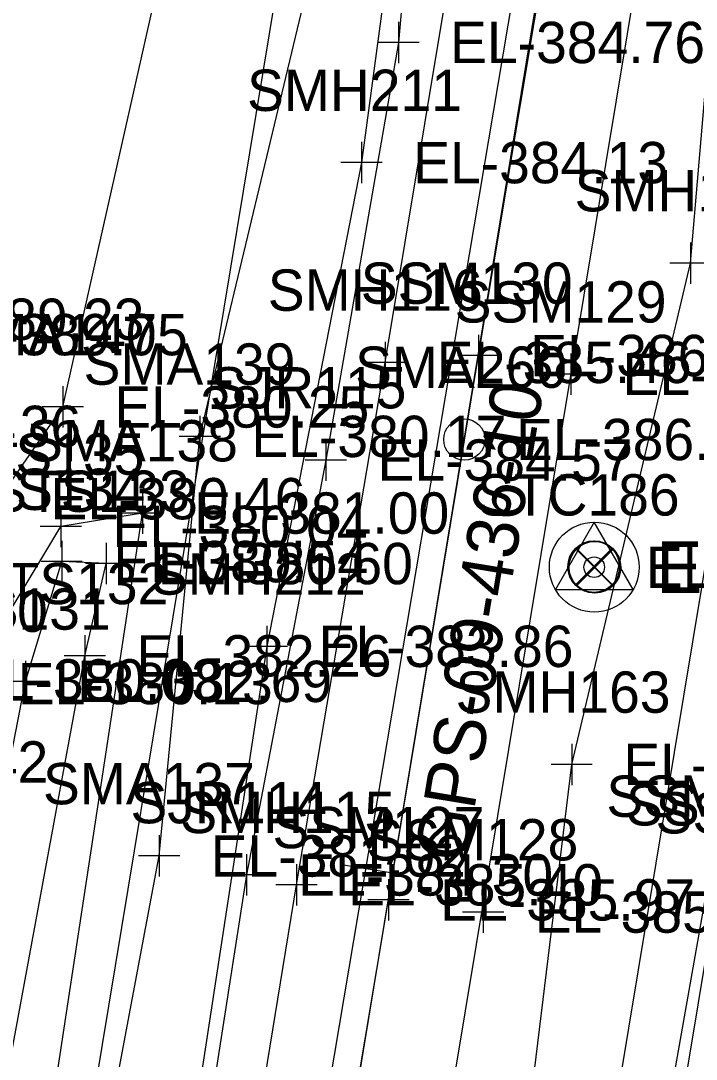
# Model space of a CAD drawing. Extents: x 1189978 to 1314812, y 571533 to 629339.
# Drawn here: x 1217500.6 to 1217566, y 621413.5 to 621514.1 of the extents above; entities that cross this region are included whole.
import ezdxf

# ---------------------------------------------------------------- set-up
doc = ezdxf.new("R2010")
doc.units = 0
for name, color, linetype in [('SURVEY - CENTERLINE - Preliminary', 7, 'Continuous'), ('SURVEY - CENTERLINE - Preliminary Text', 7, 'Continuous'), ('SURVEY - CONTROL - Check Points', 7, 'Continuous'), ('SURVEY - CONTROL - Points - Elevations', 7, 'Continuous'), ('SURVEY - CONTROL with Text', 7, 'Continuous'), ('SURVEY - DRAINAGE - Area Shapes', 7, 'Continuous'), ('SURVEY - DRAINAGE - Bridge Hydraulic Data with Text', 7, 'Continuous'), ('SURVEY - DTM - Breaklines', 7, 'Continuous'), ('SURVEY - DTM - Breaklines - Points - Elevations', 7, 'Continuous'), ('SURVEY - DTM - Breaklines - Points - Locators', 7, 'Continuous'), ('SURVEY - DTM - Breaklines - Points - Numbers', 7, 'Continuous'), ('SURVEY - DTM - Spot Points - Elevations', 7, 'Continuous'), ('SURVEY - DTM - Spot Points - Locators', 7, 'Continuous'), ('SURVEY - DTM - Spot Points - Point Numbers', 7, 'Continuous'), ('SURVEY - NON-TRANSPORTATION - Features', 7, 'Continuous'), ('SURVEY - NON-TRANSPORTATION - Features - Points - Elevations', 7, 'Continuous'), ('SURVEY - NON-TRANSPORTATION - Features - Points - Numbers', 7, 'Continuous'), ('SURVEY - PROPERTY - ROW Lines', 7, 'Continuous'), ('SURVEY - TRANSPORTATION - Features - Points - Elevations', 7, 'Continuous'), ('SURVEY - TRANSPORTATION - Features - Points - Locators', 7, 'Continuous'), ('SURVEY - TRANSPORTATION - Features - Points - Numbers', 7, 'Continuous'), ('SURVEY - TRANSPORTATION - Roads', 7, 'Continuous'), ('SURVEY - TRANSPORTATION - Roads - Points - Elevations', 7, 'Continuous'), ('SURVEY - TRANSPORTATION - Roads - Points - Locators', 7, 'Continuous'), ('SURVEY - TRANSPORTATION - Roads - Points - Numbers', 7, 'Continuous'), ('SURVEY - UTILITIES - Electric (Overhead) with Text', 7, 'Continuous'), ('SURVEY - VEGETATION - Features - Points - Elevations', 7, 'Continuous'), ('SURVEY - VEGETATION - Features - Points - Locators', 7, 'Continuous'), ('SURVEY - VEGETATION - Features - Points - Numbers', 7, 'Continuous'), ('SURVEY - VEGETATION - Features with Text', 7, 'Continuous')]:
    doc.layers.add(name, color=color, linetype=linetype)

msp = doc.modelspace()

# ---------------------------------------------------------------- linework, layer by layer
at = {"layer": 'SURVEY - CENTERLINE - Preliminary'}
msp.add_line((1217525.37, 621363.65), (1217649.69, 622116.55), dxfattribs=at)
msp.add_line((1217525.37, 621363.65), (1217649.69, 622116.55), dxfattribs=at)
at = {"layer": 'SURVEY - CENTERLINE - Preliminary Text'}
msp.add_line((1217536.58, 621431.54), (1217531.64, 621432.35), dxfattribs=at)
at = {"layer": 'SURVEY - CONTROL - Check Points'}
for p, q in [((1217557.83, 621462.99), (1217554.29, 621459.45)), ((1217554.29, 621462.99), (1217557.83, 621459.45)), ((1217557.83, 621462.99), (1217554.29, 621459.46)), ((1217554.29, 621462.99), (1217557.83, 621459.46)), ((1217557.82, 621462.98), (1217554.29, 621459.45)), ((1217554.29, 621462.98), (1217557.82, 621459.45)), ((1217557.85, 621462.95), (1217554.31, 621459.42)), ((1217554.31, 621462.95), (1217557.85, 621459.42)), ((1217557.85, 621463), (1217554.32, 621459.46)), ((1217554.32, 621463), (1217557.85, 621459.46)), ((1217557.85, 621463), (1217554.32, 621459.46)), ((1217554.32, 621463), (1217557.85, 621459.46)), ((1217557.86, 621462.96), (1217554.32, 621459.43)), ((1217554.32, 621462.96), (1217557.86, 621459.43)), ((1217557.86, 621462.94), (1217554.32, 621459.41)), ((1217554.32, 621462.94), (1217557.86, 621459.41)), ((1217557.9, 621462.97), (1217554.37, 621459.44)), ((1217554.37, 621462.97), (1217557.9, 621459.44)), ((1217557.91, 621462.96), (1217554.37, 621459.43)), ((1217554.37, 621462.96), (1217557.91, 621459.43)), ((1217557.9, 621462.93), (1217554.37, 621459.39)), ((1217554.37, 621462.93), (1217557.9, 621459.39)), ((1217557.93, 621462.93), (1217554.39, 621459.39)), ((1217554.39, 621462.93), (1217557.93, 621459.39)), ((1217557.94, 621462.92), (1217554.4, 621459.39)), ((1217554.4, 621462.92), (1217557.94, 621459.39)), ((1217557.94, 621462.94), (1217554.41, 621459.4)), ((1217554.41, 621462.94), (1217557.94, 621459.4)), ((1217557.94, 621462.93), (1217554.41, 621459.39)), ((1217554.41, 621462.93), (1217557.94, 621459.39))]:
    msp.add_line(p, q, dxfattribs=at)
for centre in [(1217556.05, 621461.21), (1217556.06, 621461.22), (1217556.06, 621461.22), (1217556.08, 621461.23), (1217556.08, 621461.18), (1217556.09, 621461.23), (1217556.09, 621461.2), (1217556.09, 621461.18), (1217556.14, 621461.21), (1217556.14, 621461.2), (1217556.14, 621461.16), (1217556.16, 621461.16), (1217556.17, 621461.17), (1217556.17, 621461.16), (1217556.17, 621461.16)]:
    msp.add_circle(centre, 2.5, dxfattribs=at)
at = {"layer": 'SURVEY - CONTROL with Text'}
for p, q in [((1217556.11, 621465.53), (1217552.34, 621459)), ((1217559.88, 621459), (1217556.11, 621465.53)), ((1217556.11, 621461.18), (1217556.11, 621461.18)), ((1217552.34, 621459), (1217559.88, 621459))]:
    msp.add_line(p, q, dxfattribs=at)
msp.add_circle((1217556.11, 621461.18), 4.35, dxfattribs=at)
at = {"layer": 'SURVEY - DRAINAGE - Area Shapes'}
msp.add_line((1217415.87, 620731.68), (1218149.36, 625079.9), dxfattribs=at)
at = {"layer": 'SURVEY - DRAINAGE - Bridge Hydraulic Data with Text'}
for p, q in [((1217565.44, 621492.61), (1217565.44, 621488.61)), ((1217567.44, 621490.61), (1217563.44, 621490.61)), ((1217553.92, 621444.08), (1217553.92, 621440.08)), ((1217555.92, 621442.08), (1217551.92, 621442.08))]:
    msp.add_line(p, q, dxfattribs=at)
msp.add_lwpolyline([(1217505.54, 621026.79), (1217497.33, 621030.97), (1217494.44, 621038.22), (1217497.2, 621080.45), (1217509.01, 621144.38), (1217516.68, 621191.71), (1217524.09, 621241.49), (1217533.15, 621294.15), (1217540.61, 621345.97), (1217548.02, 621393.69), (1217553.92, 621442.08), (1217565.44, 621490.61), (1217569.7, 621540.29), (1217578.32, 621589.37), (1217586.92, 621638.9), (1217590.67, 621661.55), (1217589.09, 621673.95), (1217587.38, 621675.54)], dxfattribs=at)
at = {"layer": 'SURVEY - DTM - Breaklines'}
for points in [[(1217387.16, 620695.14), (1217397.48, 620747.65), (1217407.02, 620809.24), (1217418.75, 620878.96), (1217427.19, 620935.15), (1217426.68, 620940.89), (1217441.48, 620996.6), (1217449.24, 621046.98), (1217458, 621101.08), (1217460.79, 621140.2), (1217471.39, 621192.44), (1217489.7, 621292.1), (1217492.93, 621335.46), (1217504.86, 621384.61), (1217513.97, 621433.22), (1217517.91, 621473.83), (1217528.68, 621518.7), (1217534.78, 621566.14), (1217543.47, 621612.64), (1217549.89, 621643.65), (1217551.17, 621685.8), (1217565.36, 621705.38)], [(1217504.64, 621476.68), (1217514.65, 621521.12), (1217528.76, 621567.82), (1217540.11, 621613.1), (1217546.43, 621644.25), (1217544.27, 621681.39), (1217509.23, 621703.06)], [(1217510.58, 621028.06), (1217508.12, 621030.69), (1217507.01, 621036.89), (1217513.63, 621077.21), (1217519.37, 621118.67), (1217522.53, 621131.01), (1217528.61, 621154.7), (1217531.08, 621195.41), (1217537.78, 621236.3), (1217543.58, 621274.68), (1217548.51, 621316.14), (1217556.97, 621353.31), (1217561.88, 621392.99), (1217568.36, 621432.01), (1217577.69, 621466.22), (1217582.73, 621504.23), (1217584.25, 621517.15), (1217585.6, 621545.35), (1217593.93, 621587.24), (1217602.31, 621624.58), (1217607.97, 621656.51), (1217606.79, 621679.18), (1217604.88, 621690.79), (1217551.17, 621685.8)], [(1217567.58, 621678.78), (1217566.65, 621676.81), (1217561.06, 621675.09), (1217559.37, 621666.41), (1217560.08, 621650.79), (1217551.98, 621602.78), (1217540.51, 621551.93), (1217533.57, 621500.33), (1217524.41, 621453.51), (1217516.18, 621399.79), (1217505.66, 621346.61), (1217497.91, 621291.92), (1217486.51, 621241.58), (1217479.66, 621189.93), (1217471.35, 621146.03), (1217465.62, 621095.91), (1217456.92, 621043.82), (1217448.31, 620989.84), (1217436.81, 620938.63)], [(1217418.06, 620739.44), (1217427.36, 620792.56), (1217436.72, 620845.05), (1217446.22, 620900.31), (1217455.61, 620954.21), (1217464.26, 621004.54), (1217473.29, 621056.89), (1217481.83, 621108.05), (1217491.34, 621163.83), (1217500.43, 621216.55), (1217508.98, 621267.02), (1217518.36, 621323.37), (1217527.29, 621375.81), (1217536.19, 621428.97), (1217544.91, 621481.66), (1217554.38, 621538.38), (1217563.54, 621592.41), (1217571.82, 621642.48), (1217577.37, 621677.13)], [(1217464.84, 621340.35), (1217476.27, 621398.1), (1217490.37, 621450.26), (1217498.46, 621467.8), (1217504.64, 621476.68)], [(1217460.01, 621236.35), (1217470.29, 621236.84), (1217483.9, 621293.02), (1217488.61, 621336.15), (1217500.02, 621385.16), (1217512.38, 621466.41), (1217504.47, 621465.12)], [(1217471.2, 621339.93), (1217481.49, 621393.54), (1217495.29, 621449.91), (1217504.47, 621465.12)], [(1217479.7, 621338.19), (1217489.92, 621392.87), (1217501.04, 621450.12), (1217504.54, 621461.71)], [(1217484.79, 621337.14), (1217495.58, 621392.02), (1217506.78, 621452.59), (1217508.86, 621461.52), (1217504.54, 621461.71)]]:
    msp.add_lwpolyline(points, dxfattribs=at)
at = {"layer": 'SURVEY - DTM - Breaklines - Points - Locators'}
for p, q in [((1217533.57, 621502.33), (1217533.57, 621498.33)), ((1217535.57, 621500.33), (1217531.57, 621500.33)), ((1217544.91, 621483.66), (1217544.91, 621479.66)), ((1217546.91, 621481.66), (1217542.91, 621481.66)), ((1217504.64, 621478.68), (1217504.64, 621474.68)), ((1217506.64, 621476.68), (1217502.64, 621476.68)), ((1217517.91, 621475.83), (1217517.91, 621471.83)), ((1217519.91, 621473.83), (1217515.91, 621473.83)), ((1217512.38, 621468.41), (1217512.38, 621464.41)), ((1217504.47, 621467.12), (1217504.47, 621463.12)), ((1217514.38, 621466.41), (1217510.38, 621466.41)), ((1217506.47, 621465.12), (1217502.47, 621465.12)), ((1217504.54, 621463.71), (1217504.54, 621459.71)), ((1217508.86, 621463.52), (1217508.86, 621459.52)), ((1217506.54, 621461.71), (1217502.54, 621461.71)), ((1217510.86, 621461.52), (1217506.86, 621461.52)), ((1217524.41, 621455.51), (1217524.41, 621451.51)), ((1217506.78, 621454.59), (1217506.78, 621450.59)), ((1217526.41, 621453.51), (1217522.41, 621453.51)), ((1217501.04, 621452.12), (1217501.04, 621448.12)), ((1217508.78, 621452.59), (1217504.78, 621452.59)), ((1217503.04, 621450.12), (1217499.04, 621450.12)), ((1217513.97, 621435.22), (1217513.97, 621431.22)), ((1217515.97, 621433.22), (1217511.97, 621433.22)), ((1217536.19, 621430.97), (1217536.19, 621426.97)), ((1217538.19, 621428.97), (1217534.19, 621428.97))]:
    msp.add_line(p, q, dxfattribs=at)
at = {"layer": 'SURVEY - DTM - Spot Points - Locators'}
msp.add_circle((1217556.1, 621461.17), 1, dxfattribs=at)
at = {"layer": 'SURVEY - NON-TRANSPORTATION - Features'}
msp.add_circle((1217543.53, 621473.53), 2, dxfattribs=at)
at = {"layer": 'SURVEY - PROPERTY - ROW Lines'}
for p, q in [((1217500.7, 621367.73), (1217557.72, 621713)), ((1217606.4, 621700.95), (1217550.03, 621359.58))]:
    msp.add_line(p, q, dxfattribs=at)
at = {"layer": 'SURVEY - TRANSPORTATION - Features - Points - Locators'}
for p, q in [((1217553.85, 621481.85), (1217553.85, 621477.85)), ((1217555.85, 621479.85), (1217551.85, 621479.85)), ((1217545.34, 621429.79), (1217545.34, 621425.79)), ((1217547.34, 621427.79), (1217543.34, 621427.79))]:
    msp.add_line(p, q, dxfattribs=at)
at = {"layer": 'SURVEY - TRANSPORTATION - Roads'}
for points in [[(1217409.51, 620742.51), (1217418.87, 620794.59), (1217428.1, 620847.79), (1217437.4, 620901.38), (1217446.45, 620953.25), (1217455.44, 621005.6), (1217463.89, 621055.84), (1217472.9, 621108.56), (1217482.31, 621162.33), (1217491.19, 621215.01), (1217500.52, 621270.57), (1217509.55, 621324.4), (1217518.06, 621374.09), (1217518.81, 621378.64), (1217527.27, 621430.43), (1217535.85, 621480.99), (1217545.48, 621538.85), (1217553.74, 621589.36), (1217562.47, 621641.97), (1217568.75, 621678.54), (1217567.58, 621678.78)], [(1217427.25, 620738.21), (1217436.59, 620791.34), (1217445.34, 620842.59), (1217455.15, 620898.88), (1217464.25, 620950.62), (1217473.39, 621002.58), (1217480.67, 621046.8), (1217490.83, 621106.73), (1217500.22, 621160.55), (1217509.53, 621215.72), (1217518.41, 621266.5), (1217527.5, 621321.85), (1217536.34, 621374.24), (1217563.48, 621537.92), (1217572.05, 621588.6), (1217580.58, 621640.89), (1217586, 621675.75), (1217587.38, 621675.54)]]:
    msp.add_lwpolyline(points, dxfattribs=at)
at = {"layer": 'SURVEY - TRANSPORTATION - Roads - Points - Locators'}
for p, q in [((1217535.85, 621482.99), (1217535.85, 621478.99)), ((1217537.85, 621480.99), (1217533.85, 621480.99)), ((1217527.27, 621432.43), (1217527.27, 621428.43)), ((1217529.27, 621430.43), (1217525.27, 621430.43))]:
    msp.add_line(p, q, dxfattribs=at)
at = {"layer": 'SURVEY - UTILITIES - Electric (Overhead) with Text'}
msp.add_lwpolyline([(1217806.14, 622777), (1217743.09, 622422.64), (1217688.2, 622113.29), (1217626.83, 621775.19), (1217569.14, 621442.23), (1217508.83, 621100.02), (1217448.24, 620751.9)], dxfattribs=at)
at = {"layer": 'SURVEY - VEGETATION - Features - Points - Locators'}
for p, q in [((1217537.15, 621513.96), (1217537.15, 621509.96)), ((1217539.15, 621511.96), (1217535.15, 621511.96)), ((1217530.13, 621473.54), (1217530.13, 621469.54)), ((1217532.13, 621471.54), (1217528.13, 621471.54)), ((1217522.44, 621433.38), (1217522.44, 621429.38)), ((1217524.44, 621431.38), (1217520.44, 621431.38))]:
    msp.add_line(p, q, dxfattribs=at)
at = {"layer": 'SURVEY - VEGETATION - Features with Text'}
msp.add_lwpolyline([(1217560.76, 621675.93), (1217556.7, 621644.18), (1217551.37, 621604.87), (1217540.8, 621553.12), (1217537.15, 621511.96), (1217530.13, 621471.54), (1217522.44, 621431.38), (1217515.9, 621389.36), (1217510.94, 621348.81), (1217502.94, 621307.06), (1217494.55, 621266.12), (1217486.37, 621220.88), (1217482.4, 621178.78), (1217475.75, 621141.85), (1217465.35, 621099.73), (1217457.55, 621059.45), (1217452.15, 621021.57), (1217443.78, 620977.07), (1217434.58, 620932.47)], dxfattribs=at)

# ---------------------------------------------------------------- texts
at = {"layer": 'SURVEY - CONTROL - Points - Elevations'}
msp.add_text('EL-385.21', height=5, dxfattribs=at).set_placement((1217562.11, 621458.68))
at = {"layer": 'SURVEY - CONTROL with Text'}
msp.add_text('GPS-09-436-10', height=5, rotation=80.6529, dxfattribs=at).set_placement((1217543.63, 621432.44))
at = {"layer": 'SURVEY - DTM - Breaklines - Points - Elevations'}
for s, p in [('EL-384.13', (1217538.57, 621498.33)), ('EL-389.23', (1217487.87, 621483.17)), ('EL-389.75', (1217492.06, 621481.68)), ('EL-386.00', (1217549.91, 621479.66)), ('EL-380.25', (1217509.64, 621474.68)), ('EL-380.17', (1217522.91, 621471.83)), ('EL-380.46', (1217503.46, 621465.8)), ('EL-381.00', (1217517.38, 621464.41)), ('EL-380.04', (1217509.47, 621463.12)), ('EL-380.54', (1217509.54, 621459.71)), ('EL-380.60', (1217513.86, 621459.52)), ('EL-383.86', (1217529.41, 621451.51)), ('EL-382.26', (1217511.78, 621450.59)), ('EL-380.03', (1217495.37, 621448.26)), ('EL-382.69', (1217506.04, 621448.12)), ('EL-380.13', (1217500.29, 621447.91)), ('EL-389.42', (1217478.56, 621440.32)), ('EL-384.44', (1217558.92, 621440.08)), ('EL-381.02', (1217518.97, 621431.22)), ('EL-385.97', (1217541.19, 621426.97))]:
    msp.add_text(s, height=4, dxfattribs=at).set_placement(p)
at = {"layer": 'SURVEY - DTM - Breaklines - Points - Numbers'}
for s, p in [('SMH211', (1217522.49, 621505.33)), ('SMH164', (1217554.2, 621495.61)), ('SSM130', (1217533.5, 621486.66)), ('SMA140', (1217493.22, 621481.68)), ('SMA139', (1217506.66, 621478.83)), ('STS136', (1217487.11, 621472.8)), ('SMA138', (1217501.09, 621471.41)), ('STS135', (1217493.23, 621470.12)), ('STS134', (1217493.3, 621466.71)), ('STS133', (1217497.62, 621466.52)), ('SMH212', (1217513.17, 621458.51)), ('STS132', (1217495.54, 621457.59)), ('STS131', (1217489.96, 621455.12)), ('STS130', (1217483.87, 621454.91)), ('SMH163', (1217542.68, 621447.08)), ('SMA137', (1217502.73, 621438.22)), ('SSM321', (1217557.28, 621437.01)), ('SSM320', (1217559.18, 621436.17)), ('SSM319', (1217562.04, 621435.4)), ('SSM127', (1217524.95, 621433.97))]:
    msp.add_text(s, height=4, dxfattribs=at).set_placement(p)
at = {"layer": 'SURVEY - DTM - Spot Points - Elevations'}
msp.add_text('EL-385.21', height=4, dxfattribs=at).set_placement((1217561.1, 621459.17))
at = {"layer": 'SURVEY - DTM - Spot Points - Point Numbers'}
msp.add_text('STC186', height=4, dxfattribs=at).set_placement((1217544.75, 621466.17))
at = {"layer": 'SURVEY - NON-TRANSPORTATION - Features - Points - Elevations'}
msp.add_text('EL-386.08', height=4, dxfattribs=at).set_placement((1217548.53, 621471.53))
at = {"layer": 'SURVEY - NON-TRANSPORTATION - Features - Points - Numbers'}
msp.add_text('SMA260', height=4, dxfattribs=at).set_placement((1217532.95, 621478.53))
at = {"layer": 'SURVEY - TRANSPORTATION - Features - Points - Elevations'}
for s, p in [('EL-385.75', (1217558.85, 621477.85)), ('EL-385.63', (1217550.34, 621425.79))]:
    msp.add_text(s, height=4, dxfattribs=at).set_placement(p)
at = {"layer": 'SURVEY - TRANSPORTATION - Features - Points - Numbers'}
for s, p in [('SSM129', (1217542.59, 621484.85)), ('SSM128', (1217534.05, 621432.79))]:
    msp.add_text(s, height=4, dxfattribs=at).set_placement(p)
at = {"layer": 'SURVEY - TRANSPORTATION - Roads - Points - Elevations'}
for s, p in [('EL-385.46', (1217540.85, 621478.99)), ('EL-385.40', (1217532.27, 621428.43))]:
    msp.add_text(s, height=4, dxfattribs=at).set_placement(p)
at = {"layer": 'SURVEY - TRANSPORTATION - Roads - Points - Numbers'}
for s, p in [('SMH116', (1217524.5, 621485.99)), ('SMH115', (1217516.03, 621435.43))]:
    msp.add_text(s, height=4, dxfattribs=at).set_placement(p)
at = {"layer": 'SURVEY - VEGETATION - Features - Points - Elevations'}
for s, p in [('EL-384.76', (1217542.15, 621509.96)), ('EL-384.57', (1217535.13, 621469.54)), ('EL-384.30', (1217527.44, 621429.38))]:
    msp.add_text(s, height=4, dxfattribs=at).set_placement(p)
at = {"layer": 'SURVEY - VEGETATION - Features - Points - Numbers'}
for s, p in [('SJR115', (1217518.89, 621476.54)), ('SJR114', (1217511.2, 621436.38))]:
    msp.add_text(s, height=4, dxfattribs=at).set_placement(p)

doc.saveas('drawing.dxf')
